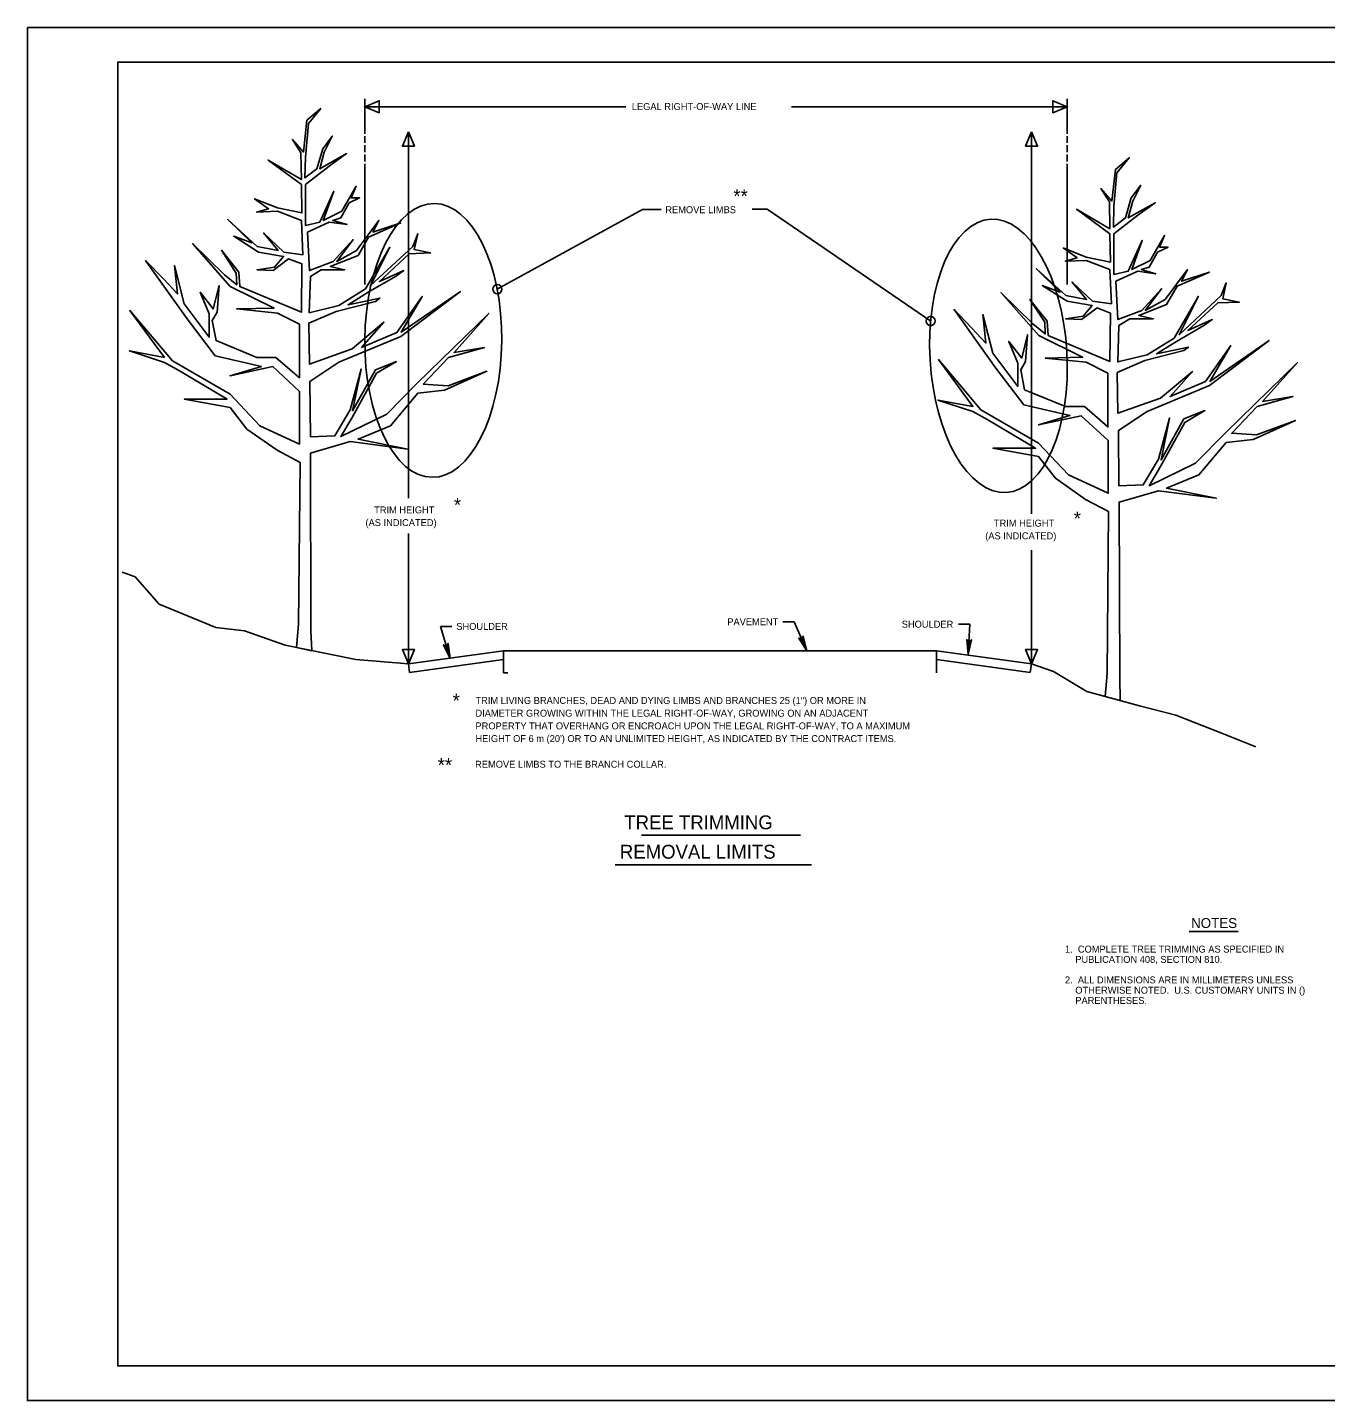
# Model space of a CAD drawing. Extents: x 639115 to 640019, y 298285 to 298879.
# Drawn here: x 639115 to 639676, y 298285 to 298879 of the extents above; entities that cross this region are included whole.
import ezdxf

# ---------------------------------------------------------------- set-up
doc = ezdxf.new("R2010")
doc.units = 0
doc.layers.add('1', color=7, linetype='Continuous')
doc.layers.add('PLT-BNDY', color=7, linetype='Continuous')

msp = doc.modelspace()

# ---------------------------------------------------------------- linework, layer by layer
at = {"layer": '1'}
for p, q in [((639260.88, 298848.28), (639260.88, 298833.28)), ((639564.61, 298848.28), (639564.61, 298833.28)), ((639260.88, 298844.91), (639373.72, 298844.91)), ((639445.33, 298844.91), (639564.61, 298844.91)), ((639260.88, 298832.26), (639260.88, 298829.28)), ((639279.75, 298834.12), (639279.75, 298675.54)), ((639549.14, 298834.12), (639549.14, 298668.85)), ((639564.61, 298832.26), (639564.61, 298829.28)), ((639260.88, 298828.28), (639260.88, 298825.28)), ((639260.88, 298824.28), (639260.88, 298821.28)), ((639564.61, 298828.28), (639564.61, 298825.28)), ((639564.61, 298824.28), (639564.61, 298821.28)), ((639260.88, 298820.28), (639260.88, 298768.06)), ((639564.61, 298820.28), (639564.61, 298768.06)), ((639380.89, 298800.45), (639317.84, 298765.82)), ((639380.89, 298800.45), (639389.02, 298800.45)), ((639428.29, 298800.68), (639434.86, 298800.68)), ((639434.86, 298800.68), (639505.55, 298752.2)), ((639279.75, 298660.26), (639279.75, 298603.89)), ((639549.14, 298653.09), (639549.14, 298603.89)), ((639441.67, 298622.04), (639446.56, 298622.04)), ((639446.56, 298622.04), (639452.06, 298609.62)), ((639293.6, 298620.13), (639298.49, 298620.13)), ((639293.6, 298620.13), (639297.78, 298606.28)), ((639517.61, 298621.09), (639522.51, 298621.09)), ((639522.51, 298621.09), (639521.79, 298607.95)), ((639279.75, 298603.89), (639320.82, 298609.62)), ((639279.75, 298603.89), (639280.27, 298600.13)), ((639280.27, 298600.13), (639320.82, 298605.79)), ((639320.82, 298609.62), (639508.06, 298609.62)), ((639320.82, 298609.62), (639320.82, 298600.07)), ((639549.14, 298603.89), (639508.06, 298609.62)), ((639508.06, 298609.62), (639508.06, 298600.07)), ((639548.62, 298600.13), (639508.06, 298605.79)), ((639549.14, 298603.89), (639548.62, 298600.13)), ((639320.82, 298600.07), (639322.71, 298600.07)), ((639380.51, 298529.75), (639449.22, 298529.75)), ((639369.12, 298517.01), (639454, 298517.01)), ((639617.27, 298488.2), (639638.42, 298488.2))]:
    msp.add_line(p, q, dxfattribs=at)
for points in [[(639940.03, 298300.23), (639940.03, 298864.23), (639154.03, 298864.23), (639154.03, 298300.23), (639940.03, 298300.23), (639940.03, 298326.59), (639740.03, 298326.59), (639740.03, 298391.26), (639940.03, 298391.26), (639940.03, 298420.23), (639740.03, 298420.23), (639740.03, 298300.23), (639818.83, 298300.23), (639818.83, 298326.59), (639818.83, 298300.23), (639895.83, 298300.23), (639895.83, 298326.59), (639895.83, 298314.27), (639940.03, 298314.27)], [(639231.35, 298611.06), (639232.25, 298621.03), (639232.88, 298691.06), (639222.96, 298696.32), (639209.93, 298705.46), (639202.62, 298714.85), (639182.85, 298718.46), (639201.33, 298718.46), (639180.7, 298730.74), (639174.25, 298734.35), (639159.1, 298739.28), (639174.25, 298736.52), (639159.31, 298756.82), (639177.69, 298735.07), (639202.62, 298720.63), (639215.52, 298706.91), (639232.71, 298698.96), (639232.64, 298721.75), (639221.05, 298732.5), (639202.62, 298728.57), (639216.16, 298732.62), (639196.17, 298737.24), (639184.14, 298753.13), (639166.08, 298778.41), (639173.82, 298770.46), (639179.84, 298763.96), (639178.55, 298776.24), (639182.85, 298759.63), (639193.59, 298745.18), (639193.59, 298755.3), (639189.73, 298764.68), (639195.31, 298757.46), (639197.89, 298767.57), (639197.03, 298756.02), (639194.88, 298752.41), (639196.6, 298743.74), (639214.23, 298736.52), (639222.4, 298736.52), (639232.61, 298727.67), (639232.61, 298750.88), (639223.15, 298755.66), (639205.52, 298757.46), (639221.64, 298757.82), (639202.73, 298767.21), (639186.39, 298785.71), (639200.15, 298772.27), (639205.52, 298767.93), (639205.31, 298772.99), (639198.86, 298782.87), (639206.38, 298773.35), (639206.81, 298767.21), (639233.47, 298756.04), (639233.68, 298776.94), (639227.88, 298779.13), (639221.21, 298774.07), (639214.34, 298774.43), (639221.86, 298775.52), (639225.73, 298780.21), (639214.98, 298782.02), (639204.23, 298788.88), (639211.97, 298785.99), (639201.65, 298796.1), (639214.34, 298784.54), (639223.36, 298782.74), (639217.13, 298790.32), (639225.94, 298782.02), (639234.11, 298780.93), (639233.47, 298795.74), (639223.15, 298799.71), (639214.12, 298799.35), (639219.28, 298800.79), (639213.26, 298805.13), (639223.15, 298801.16), (639233.68, 298798.99), (639233.47, 298811.27), (639219.07, 298821.82), (639233.47, 298813.43), (639233.25, 298824.99), (639229.6, 298830.77), (639234.33, 298825.35), (639235.83, 298839.07), (639241.85, 298844.13), (639236.48, 298837.63), (639235.19, 298823.18), (639234.97, 298814.16), (639240.13, 298818.13), (639242.71, 298826.79), (639246.79, 298832.21), (639243.35, 298825.35), (639241.42, 298818.13), (639253.03, 298824.65), (639245.5, 298819.21), (639235.19, 298811.27), (639235.19, 298793.57), (639241.42, 298795.02), (639247.44, 298808.38), (639242.92, 298795.74), (639250.88, 298799.71), (639257.11, 298810.54), (639254.96, 298805.49), (639258.61, 298805.49), (639254.1, 298803.32), (639250.45, 298796.82), (639247.01, 298795.74), (639253.24, 298793.93), (639245.5, 298795.02), (639236.05, 298790.68), (639236.91, 298774.07), (639247.22, 298778.04), (639255.82, 298787.43), (639248.73, 298778.04), (639257.33, 298782.74), (639267, 298795.74), (639264.42, 298790.68), (639276.45, 298794.66), (639262.48, 298788.52), (639257.97, 298780.57), (639245.93, 298775.88), (639252.17, 298774.43), (639242.06, 298774.43), (639237.34, 298771.55), (639236.88, 298755.79), (639249.59, 298758.91), (639261.19, 298766.13), (639271.73, 298784.18), (639263.34, 298767.57), (639281.61, 298784.54), (639283.76, 298789.96), (639282.26, 298783.1), (639289.35, 298781.66), (639280.11, 298781.29), (639267.21, 298769.38), (639277.74, 298774.07), (639274.09, 298771.55), (639262.27, 298764.68), (639253.67, 298759.27), (639267.43, 298762.16), (639265.49, 298760.71), (639248.51, 298756.38), (639236.64, 298751.25), (639236.91, 298733.6), (639255.39, 298740.13), (639269.15, 298751.68), (639259.47, 298740.83), (639274.74, 298747.27), (639285.7, 298762.88), (639276.67, 298747.35), (639302.25, 298765.07), (639276.45, 298745.55), (639249.59, 298734.38), (639237.12, 298726.12), (639237.34, 298702.14), (639247.87, 298702.57), (639254.53, 298713.77), (639259.26, 298731.46), (639255.61, 298713.41), (639265.49, 298731.1), (639274.52, 298734.71), (639265.92, 298729.66), (639255.39, 298710.52), (639250.45, 298702.21), (639270.44, 298711.96), (639283.55, 298725.32), (639314.5, 298755.53), (639299.45, 298738.68), (639312.57, 298740.83), (639297.09, 298736.52), (639286.13, 298724.96), (639296.87, 298724.24), (639313.64, 298730.51), (639295.37, 298722.25), (639283.76, 298720.99), (639271.94, 298706.91), (639257.97, 298701.13), (639279.46, 298696.8), (639254.53, 298700.05), (639237.41, 298695.12), (639237.5, 298618.34), (639237.92, 298609.62), (639231.35, 298611.06)], [(639580.93, 298589.8), (639581.83, 298599.77), (639582.46, 298669.81), (639572.54, 298675.06), (639559.51, 298684.21), (639552.2, 298693.6), (639532.43, 298697.21), (639550.91, 298697.21), (639530.28, 298709.49), (639523.83, 298713.1), (639508.68, 298718.02), (639523.83, 298715.26), (639508.89, 298735.56), (639527.27, 298713.82), (639552.2, 298699.37), (639565.1, 298685.65), (639582.29, 298677.71), (639582.22, 298700.5), (639570.63, 298711.24), (639552.2, 298707.32), (639565.74, 298711.36), (639545.75, 298715.98), (639533.72, 298731.87), (639515.66, 298757.15), (639523.4, 298749.21), (639529.42, 298742.71), (639528.13, 298754.98), (639532.43, 298738.37), (639543.17, 298723.93), (639543.17, 298734.04), (639539.31, 298743.43), (639544.89, 298736.21), (639547.47, 298746.32), (639546.61, 298734.76), (639544.46, 298731.15), (639546.18, 298722.48), (639563.81, 298715.26), (639571.98, 298715.26), (639582.19, 298706.42), (639582.19, 298729.63), (639572.73, 298734.4), (639555.1, 298736.21), (639571.22, 298736.57), (639552.31, 298745.96), (639535.97, 298764.45), (639549.73, 298751.01), (639555.1, 298746.68), (639554.89, 298751.73), (639548.44, 298761.61), (639555.96, 298752.1), (639556.39, 298745.96), (639583.05, 298734.79), (639583.26, 298755.68), (639577.46, 298757.87), (639570.79, 298752.82), (639563.92, 298753.18), (639571.44, 298754.26), (639575.31, 298758.96), (639564.56, 298760.76), (639553.81, 298767.62), (639561.55, 298764.73), (639551.23, 298774.84), (639563.92, 298763.29), (639572.94, 298761.48), (639566.71, 298769.07), (639575.52, 298760.76), (639583.69, 298759.68), (639583.05, 298774.48), (639572.73, 298778.46), (639563.7, 298778.09), (639568.86, 298779.54), (639562.84, 298783.87), (639572.73, 298779.9), (639583.26, 298777.73), (639583.05, 298790.01), (639568.65, 298800.56), (639583.05, 298792.18), (639582.83, 298803.73), (639579.18, 298809.51), (639583.91, 298804.09), (639585.41, 298817.82), (639591.43, 298822.87), (639586.06, 298816.37), (639584.77, 298801.93), (639584.55, 298792.9), (639589.71, 298796.87), (639592.29, 298805.54), (639596.37, 298810.96), (639592.93, 298804.09), (639591, 298796.87), (639602.61, 298803.4), (639595.08, 298797.96), (639584.77, 298790.01), (639584.77, 298772.32), (639591, 298773.76), (639597.02, 298787.12), (639592.5, 298774.48), (639600.46, 298778.46), (639606.69, 298789.29), (639604.54, 298784.23), (639608.19, 298784.23), (639603.68, 298782.07), (639600.03, 298775.57), (639596.59, 298774.48), (639602.82, 298772.68), (639595.08, 298773.76), (639585.63, 298769.43), (639586.49, 298752.82), (639596.8, 298756.79), (639605.4, 298766.18), (639598.31, 298756.79), (639606.9, 298761.48), (639616.58, 298774.48), (639614, 298769.43), (639626.03, 298773.4), (639612.06, 298767.26), (639607.55, 298759.32), (639595.51, 298754.62), (639601.75, 298753.18), (639591.64, 298753.18), (639586.92, 298750.29), (639586.46, 298734.53), (639599.17, 298737.65), (639610.77, 298744.87), (639621.31, 298762.93), (639612.92, 298746.32), (639631.19, 298763.29), (639633.34, 298768.71), (639631.84, 298761.85), (639638.93, 298760.4), (639629.69, 298760.04), (639616.79, 298748.12), (639627.32, 298752.82), (639623.67, 298750.29), (639611.85, 298743.43), (639603.25, 298738.01), (639617.01, 298740.9), (639615.07, 298739.46), (639598.09, 298735.12), (639586.22, 298729.99), (639586.49, 298712.35), (639604.97, 298718.87), (639618.73, 298730.43), (639609.05, 298719.57), (639624.32, 298726.02), (639635.28, 298741.62), (639626.25, 298726.1), (639651.83, 298743.82), (639626.03, 298724.29), (639599.17, 298713.12), (639586.7, 298704.87), (639586.92, 298680.88), (639597.45, 298681.32), (639604.11, 298692.51), (639608.84, 298710.21), (639605.19, 298692.15), (639615.07, 298709.85), (639624.1, 298713.46), (639615.5, 298708.4), (639604.97, 298689.26), (639600.03, 298680.96), (639620.02, 298690.71), (639633.13, 298704.07), (639664.08, 298734.27), (639649.03, 298717.43), (639662.14, 298719.57), (639646.67, 298715.26), (639635.71, 298703.71), (639646.45, 298702.99), (639663.22, 298709.25), (639644.95, 298701), (639633.34, 298699.74), (639621.52, 298685.65), (639607.55, 298679.87), (639629.04, 298675.54), (639604.11, 298678.79), (639586.99, 298673.87), (639587.31, 298597.89), (639587.49, 298588.04), (639580.93, 298589.8)], [(639279.75, 298603.89), (639257.06, 298605.8), (639226.49, 298612.01), (639208.81, 298618.22), (639196.4, 298619.65), (639172.04, 298629.69), (639161.53, 298641.63), (639155.93, 298643.59)], [(639450.28, 298615.54), (639449.97, 298615.15), (639452.06, 298609.62), (639450.28, 298615.54), (639450.4, 298615.94), (639452.06, 298609.62), (639449.41, 298614.9), (639448.92, 298614.92), (639452.06, 298609.62), (639448.51, 298615.1), (639448.92, 298614.92)], [(639296.74, 298612.37), (639296.38, 298612.02), (639297.78, 298606.28), (639296.74, 298612.37), (639296.91, 298612.75), (639297.78, 298606.28), (639295.79, 298611.84), (639295.31, 298611.92), (639297.78, 298606.28), (639294.93, 298612.15), (639295.31, 298611.92)], [(639522.9, 298614.03), (639522.44, 298613.83), (639521.79, 298607.95), (639522.9, 298614.03), (639523.18, 298614.33), (639521.79, 298607.95), (639521.82, 298613.86), (639521.4, 298614.1), (639521.79, 298607.95), (639521.12, 298614.44), (639521.4, 298614.1)], [(639646.09, 298567.98), (639630.94, 298574.04), (639611.59, 298581.68), (639595.83, 298585.74), (639573.02, 298591.95), (639558.69, 298600.55), (639549.14, 298603.89)]]:
    msp.add_lwpolyline(points, dxfattribs=at)
for points in [[(639260.88, 298844.91), (639267.1, 298842.32), (639267.1, 298847.5)], [(639564.61, 298844.91), (639558.38, 298847.5), (639558.38, 298842.32)], [(639279.75, 298834.12), (639277.15, 298827.9), (639282.34, 298827.9)], [(639549.14, 298834.12), (639546.55, 298827.9), (639551.73, 298827.9)], [(639279.75, 298603.89), (639277.15, 298610.11), (639282.34, 298610.11)], [(639549.14, 298603.89), (639546.55, 298610.11), (639551.73, 298610.11)]]:
    msp.add_lwpolyline(points, close=True, dxfattribs=at)
for centre in [(639318.15, 298766.01), (639505.55, 298752.2)]:
    msp.add_circle(centre, 1.98, dxfattribs=at)
for centre, major_axis in [((639290.49, 298743.84), (0.48, 59.23)), ((639534.85, 298737.17), (-3.36, 59.13))]:
    msp.add_ellipse(centre, major_axis=major_axis, ratio=0.5, dxfattribs=at)
at = {"layer": 'PLT-BNDY'}
msp.add_lwpolyline([(639115.03, 298879.23), (639956.03, 298879.23), (639956.03, 298285.23), (639115.03, 298285.23)], close=True, dxfattribs=at)

# ---------------------------------------------------------------- texts
at = {"layer": '1'}
for s, height, p in [('LEGAL RIGHT-OF-WAY LINE', 2.9997, (639376.32, 298843.52)), ('**', 6, (639420.24, 298803.25)), ('REMOVE LIMBS', 2.9997, (639390.82, 298798.88)), ('*', 6, (639299.39, 298669.64)), ('TRIM HEIGHT', 2.9997, (639264.91, 298669.02)), ('*', 6, (639567.4, 298663.8)), ('(AS INDICATED)', 2.9997, (639261.17, 298663.52)), ('TRIM HEIGHT', 2.9997, (639532.87, 298663.3)), ('(AS INDICATED)', 2.9997, (639529.13, 298657.8)), ('SHOULDER', 3, (639300.43, 298618.62)), ('PAVEMENT', 3, (639417.6, 298620.63)), ('SHOULDER', 3, (639493.03, 298619.57)), ('TRIM LIVING BRANCHES, DEAD AND DYING LIMBS AND BRANCHES 25 (1") OR MORE IN', 3, (639308.72, 298586.58)), ('DIAMETER GROWING WITHIN THE LEGAL RIGHT-OF-WAY, GROWING ON AN ADJACENT', 3, (639308.72, 298581.08)), ('PROPERTY THAT OVERHANG OR ENCROACH UPON THE LEGAL RIGHT-OF-WAY, TO A MAXIMUM ', 3, (639308.72, 298575.58)), ("HEIGHT OF 6 m (20') OR TO AN UNLIMITED HEIGHT, AS INDICATED BY THE CONTRACT ITEMS.", 3, (639308.72, 298570.08)), ('REMOVE LIMBS TO THE BRANCH COLLAR.', 3, (639308.58, 298558.99)), ('TREE TRIMMING', 6, (639373.08, 298532.37)), ('REMOVAL LIMITS', 6, (639371.17, 298519.63)), ('NOTES', 4.32, (639618.13, 298489.63)), ('1.  COMPLETE TREE TRIMMING AS SPECIFIED IN ', 3, (639563.61, 298479.01)), ('    PUBLICATION 408, SECTION 810.', 3, (639563.61, 298474.57)), ('2.  ALL DIMENSIONS ARE IN MILLIMETERS UNLESS', 3, (639563.61, 298465.69)), ('    OTHERWISE NOTED.  U.S. CUSTOMARY UNITS IN ()', 3, (639563.61, 298461.24)), ('    PARENTHESES.', 3, (639563.61, 298456.8))]:
    msp.add_text(s, height=height, dxfattribs=at).set_placement(p)
for s, p in [('*', (639298.86, 298584.99)), ('**', (639292.4, 298557.13))]:
    msp.add_text(s, height=6, rotation=360, dxfattribs=at).set_placement(p)

doc.saveas('drawing.dxf')
